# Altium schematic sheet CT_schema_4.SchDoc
size 151 x 142 mm
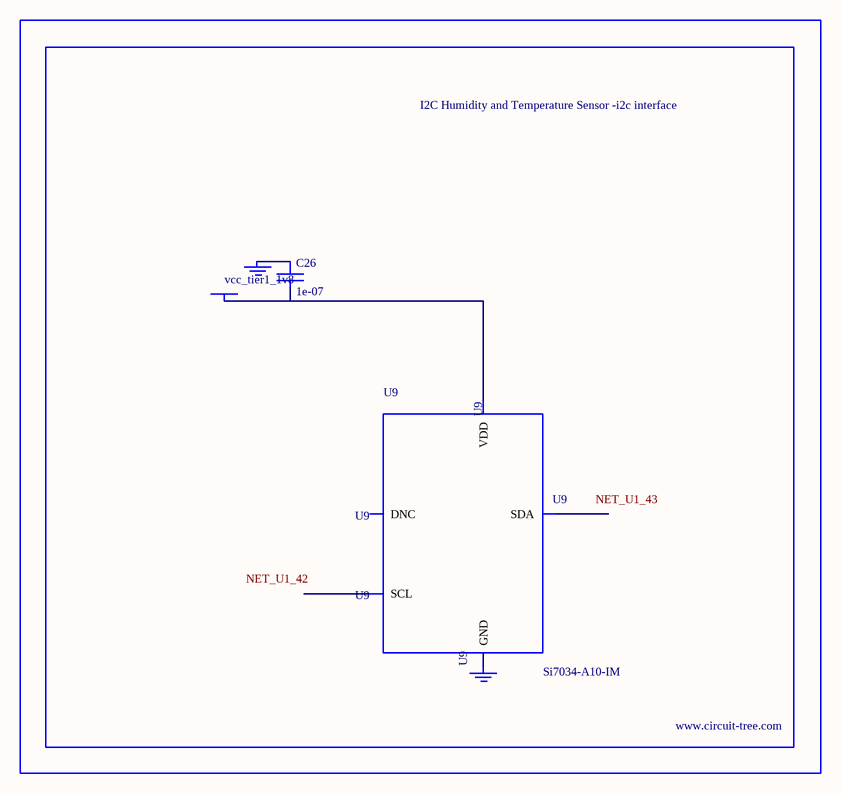
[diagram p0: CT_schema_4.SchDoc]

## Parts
BORDER3  (no value)
C26  1e-07  [C0402]
GND_INSTANCE_3_0  (no value)
GND_INSTANCE_3_1  (no value)
POWER_INSTANCE_3_0  vcc_tier1_1v8
U9  Si7034-A10-IM  [SI7034-A10-IM]

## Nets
NetC26_1: C26.1 GND_INSTANCE_3_0.0(GND)
NetC26_2: C26.2 POWER_INSTANCE_3_0.0(PWR) U9.1(VDD)
NetGND_INSTANCE_3_1_0: GND_INSTANCE_3_1.0(GND) U9.5(GND)

Not connected (* = marked no-connect by the designer): U9 2(SCL) 3(DNC) 4(SDA)

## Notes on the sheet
- Labels drawn without touching a wire or pin: NET_U1_42, NET_U1_43

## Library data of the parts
BORDER3 = BORDER_PAGE3
C26 = C0402C104K3RACTU
GND_INSTANCE_3_0 GND_INSTANCE_3_1 = GND
POWER_INSTANCE_3_0 = PWR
